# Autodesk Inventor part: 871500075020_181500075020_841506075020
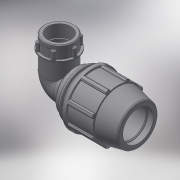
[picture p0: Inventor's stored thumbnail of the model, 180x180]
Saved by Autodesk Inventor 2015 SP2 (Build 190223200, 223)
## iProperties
Created: 2017-02
Part Number: 871500075020_181500075020_841506075020
Material: Generic
Description: PLASSON 90° ELBOW FEMALE ADAPTOR 75-2"
Document SubType Name: Modeling
Designer: KIM
Mass: 1287.77 g
Surface Area: 1760.4 cm^2
Volume: 1287.77 cm^3
Density: 1 g/cm^3
Appearance: Default
Author: KIM
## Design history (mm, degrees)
derived "87150.ipt"
feature "Solid1::87150.ipt"
tag "TaggingFeature1"
body "Solid1"
other parameters: "d2" = 75, "d4" = 16.08333, "d5" = 48.25, "d7" = 132, "d9" = 27.57143, "d11" = 6.43333, "d13" = 120 deg, "d14" = 97.5, "d15" = 12 deg, "d16" = 114.84, "d18" = 3.75, "d19" = 35 deg, "d20" = 17.5 deg, "d21" = 122.76, "d23" = 0, "d25" = 360 deg, "d27" = 2.64, "d33" = 1.5, "d42" = 71.41, "d43" = 3.96, "d46" = 2.25, "d51" = 193, "d68" = 12.86667, "d73" = 73.6528, "d75" = 84.70072, "d76" = 56.656, "d77" = 33, "d79" = 22.6624, "d80" = 1.69968, "d83" = 0, "d84" = 0, "d91" = 99, "d93" = 137, "d94" = 56.656, "d95" = 39.6592, "d96" = 12.86667, "d97" = 50 deg, "d98" = 50.9904, "d99" = 0.5, "d100" = 0.5, "d101" = 10, "d102" = 73.6528, "d103" = 25.8, "d104" = 0, "d108" = 360 deg, "d110" = 2.20958, "d111" = 8.8, "d112" = 0, "d113" = 3.21667, "d114" = 3.21667, "d115" = 111.3948, "d_" = 75, "E_" = 132, "A_" = 193, "l_" = 137, "Rp_" = 56.656, "d105" = 11.04792
